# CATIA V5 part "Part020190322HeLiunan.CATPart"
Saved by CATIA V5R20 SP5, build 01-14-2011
Part number: 花瓶
Bounding box of the stored display mesh (mm): x -33.999 to 33.999, y -33.999 to 33.964, z 0 to 100
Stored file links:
  E:\180131213何浏楠\Part020190322HeLiunan.CATPart
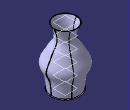
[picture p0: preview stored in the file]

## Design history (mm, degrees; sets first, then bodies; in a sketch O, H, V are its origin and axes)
Body1 (main body)
  Plane1: type Offset, RefPlane xy-plane, Offset 20
  Plane2: type Offset, RefPlane Plane1, Offset 20
  Plane3: type Offset, RefPlane Plane2, Offset 20
  Plane4: type Offset, RefPlane Plane3, Offset 20
  Plane5: type Offset, RefPlane Plane4, Offset 20
  Sketch1 on Plane5, origin (0, 0, 100), H (1, 0, 0), V (0, 1, 0)
    circle A1 centre (0, 0) radius 20
    radius A1 = 20
  Sketch2 on Plane4, origin (0, 0, 80), H (1, 0, 0), V (0, 1, 0)
    circle A1 centre (0, 0) radius 15
    radius A1 = 15
  Sketch3 on Plane3, origin (0, 0, 60), H (1, 0, 0), V (0, 1, 0)
    circle A1 centre (0, 0) radius 25
    radius A1 = 25
  Sketch4 on Plane2, origin (0, 0, 40), H (1, 0, 0), V (0, 1, 0)
    circle A1 centre (0, 0) radius 34
    radius A1 = 34
  Sketch5 on Plane1, origin (0, 0, 20), H (1, 0, 0), V (0, 1, 0)
    circle A1 centre (0, 0) radius 27
    point P1 (27, 0)
    radius A1 = 27
    coincidence: A1 P1, P1 H
  Sketch6 on xy-plane, origin (0, 0, 0), H (1, 0, 0), V (0, 1, 0)
    circle A1 centre (0, 0) radius 25
    radius A1 = 25
  Loft1: solid, Sections (Sketch1; Sketch2; Sketch3; Sketch4; Sketch5; Sketch6)
  Plane6: linked copy from another document
  Shell1: ExtOffset 0, Face face of Loft1, IntOffset 1
  Shell2: ExtOffset 0, Face face of Loft1, IntOffset 1
Current feature: Shell1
